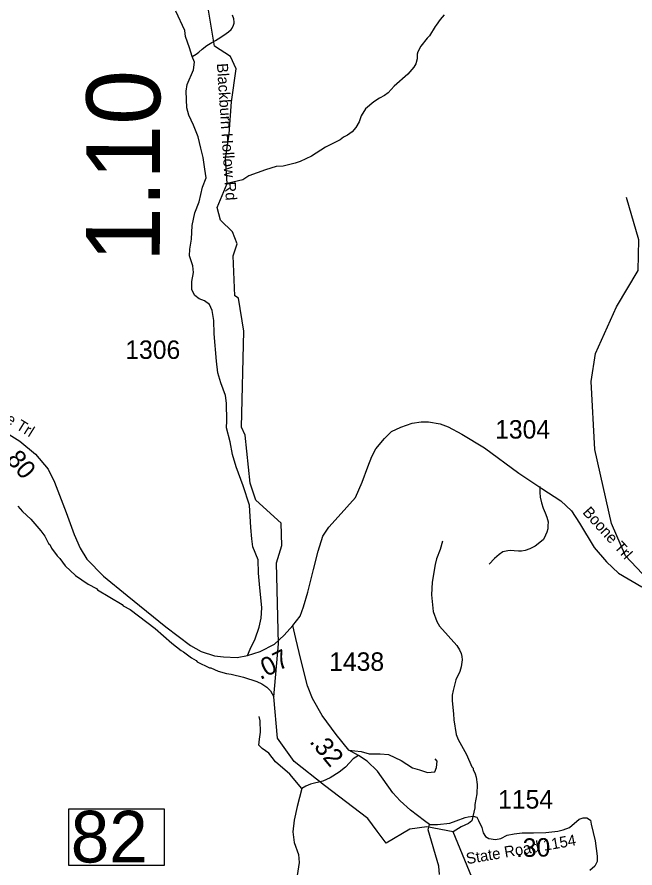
# Model space of a CAD drawing. Extents: x 1248224 to 1454986, y 825081 to 985870.
# Drawn here: x 1310144 to 1314327, y 885943 to 891703 of the extents above; entities that cross this region are included whole.
import ezdxf

# ---------------------------------------------------------------- set-up
doc = ezdxf.new("R2010")
doc.units = 0
for name, color, linetype in [('Exist Hydrographic Creek Single Shore', 7, 'Continuous'), ('Exist Hydrographic Misc Water Feature', 7, 'Continuous'), ('Exist Road Non-System Type 51', 7, 'Continuous'), ('Exist Road Secondary Mileage Hundredths English Label', 7, 'Continuous'), ('Exist Road Secondary Structure Standard Bridge Number Label', 7, 'Continuous'), ('Exist Road Secondary Type 41 Attributed', 7, 'Continuous'), ('Exist Road Secondary Type 51 Attributed', 7, 'Continuous'), ('Exist Road Secondary Type 51 Label', 7, 'Continuous'), ('Exist Road Secondary Type 51 Number Label', 7, 'Continuous')]:
    doc.layers.add(name, color=color, linetype=linetype)

msp = doc.modelspace()

# ---------------------------------------------------------------- linework, layer by layer
at = {"layer": 'Exist Hydrographic Creek Single Shore'}
for points in [[(1311907.8, 886821.5), (1311883.5, 887102.1), (1311913.1, 887460.4), (1311901.1, 888008.9), (1311937.1, 888126.3), (1311932, 888277.4), (1311761, 888431.9), (1311722.1, 888547.6), (1311688, 888873.3), (1311664, 888926.3), (1311679, 889576), (1311643, 889799.9), (1311618, 889816.9), (1311608.1, 890086.3), (1311634, 890167.7), (1311603, 890250.5), (1311522, 890327.6), (1311498.1, 890413.5), (1311567.8, 890576.8), (1311556, 890743.8), (1311579.4, 890912), (1311595.7, 891130), (1311628.4, 891353.6), (1311590.3, 891435.3), (1311482, 891507), (1311438, 891763.9)], [(1313592.1, 885795.1), (1313391.9, 885824.4), (1313221.7, 885881.2), (1313095.9, 886188.8), (1312918, 886222.1), (1312803.6, 886205.8), (1312643.6, 886111.4), (1312581.7, 886193)]]:
    msp.add_lwpolyline(points, dxfattribs=at)
at = {"layer": 'Exist Hydrographic Misc Water Feature'}
for points in [[(1313036.2, 891718), (1313007.3, 891686.8), (1312982.1, 891647.5), (1312973.9, 891639.7), (1312936.1, 891576.9), (1312919.7, 891561.3), (1312878.1, 891506.5), (1312857, 891467.2), (1312852.6, 891451.3), (1312853.7, 891419.3), (1312842.8, 891387.6), (1312830.1, 891364), (1312788.8, 891317.2), (1312696.4, 891235.9), (1312657.1, 891191.1), (1312632.6, 891171.8), (1312598.1, 891154.8), (1312559.4, 891129.9), (1312502, 891081.6), (1312474.6, 891034.4), (1312459.6, 890994.8), (1312438.5, 890955.5), (1312413.6, 890926.1), (1312380.9, 890903.1), (1312354.6, 890889.9), (1312332, 890872.5), (1312232.6, 890821.5), (1312136.9, 890762.2), (1312059.8, 890724.5), (1312027.4, 890713.4), (1311946.8, 890693.7), (1311898.8, 890691.2), (1311826.2, 890669.2), (1311713, 890628.5), (1311672.2, 890601.8), (1311567.8, 890576.8)], [(1315613.2, 885905.6), (1315634.2, 886089), (1315686.2, 886179.8), (1315689.2, 886321), (1315487.1, 886567.9), (1315408.2, 886796.1), (1315303.2, 886913.1), (1315040.1, 887069.4), (1314905.2, 887380.6), (1314710.2, 887594.7), (1314680.2, 887736.5), (1314647.1, 887779.8), (1314376.2, 887936.2), (1314262.2, 888056.7), (1314167.1, 888275.3), (1314054.1, 888776.5), (1314031.1, 889236.7), (1314060.1, 889426.4), (1314201.1, 889742), (1314349.1, 889988.6), (1314354.1, 890195.3), (1314269.1, 890482.6)], [(1310149.5, 888392.4), (1310180.4, 888355.5), (1310237, 888303.9), (1310304.8, 888226), (1310331.7, 888189.2), (1310358.4, 888140.4), (1310366.2, 888132.2), (1310377.5, 888107.9), (1310416.1, 888056.9), (1310433.6, 888038.3), (1310470.3, 887989.3), (1310540.4, 887923.3), (1310626.8, 887864.8), (1310682, 887835.2), (1310689.8, 887827), (1310855, 887726.2), (1310862.7, 887718), (1310910.1, 887692.7), (1311078.5, 887563.8), (1311191.7, 887464.6), (1311254.4, 887414.7), (1311270.2, 887406.3), (1311325, 887364.8), (1311356.6, 887347.9), (1311364.3, 887339.6), (1311447.2, 887297.2), (1311455.1, 887297), (1311506.6, 887275.5), (1311562.2, 887259.9), (1311594, 887255), (1311677.5, 887234.6), (1311766.7, 887206), (1311802.3, 887189), (1311835.7, 887166.1), (1311859, 887141.4), (1311883.5, 887102.1)], [(1313024, 888155.4), (1313008.4, 888099.8), (1312984.6, 888036.6), (1312973.5, 887996.9), (1312954.2, 887877.5), (1312949.7, 887791.6), (1312960.5, 887679.4), (1312984.7, 887612.7), (1313003.8, 887580.2), (1313120.1, 887448.9), (1313139.3, 887420.3), (1313150.7, 887396), (1313156.1, 887375.8), (1313157.5, 887351.8), (1313150.1, 887304), (1313141.2, 887272.3), (1313113.6, 887217.1), (1313095.6, 887145.6), (1313090.7, 887113.8), (1313089.6, 887073.8), (1313099.1, 886985.6), (1313099.9, 886945.6), (1313117.3, 886847.1), (1313130.3, 886812.7), (1313187.4, 886711.1), (1313223.1, 886628.2), (1313230.9, 886617.9), (1313230.6, 886609.9), (1313245.8, 886581.5), (1313253.1, 886557.3), (1313257.7, 886509.1), (1313256, 886445.2), (1313244, 886373.6), (1313243.3, 886349.6), (1313222.9, 886262.2), (1313200.3, 886244.9), (1313149.7, 886222.4), (1313095.9, 886188.8)], [(1312581.7, 886193), (1312517.9, 886277.1), (1312225.1, 886502.1), (1312020.1, 886663.8), (1311907.8, 886821.5)]]:
    msp.add_lwpolyline(points, dxfattribs=at)
at = {"layer": 'Exist Road Non-System Type 51'}
for points in [[(1311330, 891437.1), (1311356.3, 891452.4), (1311374.6, 891466.1), (1311397, 891485.6), (1311429.8, 891510.8), (1311462.2, 891532.1), (1311488.5, 891545.4), (1311504.9, 891555.1), (1311531.3, 891572.6), (1311559.7, 891591.8), (1311575.9, 891603.5), (1311594.4, 891619.1), (1311600.6, 891628.8), (1311609, 891648.7), (1311613.3, 891662.6), (1311613.4, 891668.6), (1311612.1, 891690.6), (1311602.6, 891716.8)], [(1313684, 888524.4), (1313682.9, 888484.3), (1313686.1, 888454.3), (1313693.3, 888414.1), (1313706.5, 888379.8), (1313719.8, 888347.3), (1313731, 888317.1), (1313738.4, 888286.9), (1313737.7, 888258.9), (1313737.3, 888238.9), (1313730.8, 888217), (1313722.2, 888197.2), (1313713.9, 888181.3), (1313705.6, 888165.5), (1313685.2, 888148.1), (1313670.8, 888138.4), (1313650.4, 888120.8), (1313616.1, 888103.7), (1313583.8, 888092.3), (1313559.7, 888087), (1313537.7, 888087.4), (1313509.7, 888090.2), (1313485.8, 888092.7), (1313465.7, 888091.1), (1313433.4, 888083.9), (1313407, 888064.4), (1313376.4, 888039.2), (1313339.4, 887999.9)], [(1312071.4, 886480.7), (1311991.3, 886577.8), (1311894.2, 886662.9), (1311848.1, 886721.1), (1311804.4, 886752.7), (1311780.2, 886774.6), (1311785, 886815.9), (1311792.3, 886862), (1311789.9, 886939.7), (1311782.6, 886968.9)], [(1312390.9, 886741.7), (1312430.6, 886735.7), (1312474.3, 886730.9), (1312527.7, 886716.3), (1312602.9, 886716.3), (1312658.7, 886711.4), (1312743.7, 886670.1), (1312821.3, 886621.6), (1312867.5, 886607), (1312923.3, 886590), (1312971.8, 886594.8), (1312984, 886624), (1312988.8, 886665.3), (1312974.3, 886682.3)], [(1312454.9, 886705.7), (1312418.5, 886682.3), (1312367.5, 886626.4), (1312323.8, 886592.4), (1312263.1, 886553.6), (1312214.6, 886531.7), (1312129.6, 886509.8), (1312098.1, 886497.7), (1312071.4, 886480.7)], [(1312071.4, 886480.7), (1312040.5, 886360.3), (1312021.1, 886268), (1312011.4, 886187.8), (1312021.1, 886115), (1312050.2, 886034.8), (1312055.1, 885981.4), (1312028.4, 885821.1)]]:
    msp.add_lwpolyline(points, dxfattribs=at)
at = {"layer": 'Exist Road Secondary Structure Standard Bridge Number Label'}
msp.add_lwpolyline([(1310495.6, 886343), (1311139.7, 886343), (1311139.7, 885960.7), (1310495.6, 885960.7)], close=True, dxfattribs=at)
at = {"layer": 'Exist Road Secondary Type 41 Attributed'}
msp.add_lwpolyline([(1311703.3, 887381.1), (1311721.9, 887425), (1311756.4, 887494.1), (1311782.8, 887573.3), (1311797, 887634.3), (1311801.1, 887703.4), (1311784.9, 887863.9), (1311778.8, 887939.1), (1311776.7, 888028.5), (1311740.2, 888117.9), (1311734.1, 888170.7), (1311726, 888247.9), (1311717.9, 888399.2), (1311675.2, 888529.2), (1311626.5, 888659.3), (1311602.1, 888742.6), (1311587.9, 888827.9), (1311561.8, 888922.3), (1311563.9, 888969.1), (1311561.8, 889088.9), (1311555.8, 889141.8), (1311523.3, 889227.1), (1311503, 889294.2), (1311494.9, 889373.4), (1311478.6, 889559.2), (1311476.6, 889648.6), (1311464.4, 889717.6), (1311446.2, 889758.3), (1311413.7, 889782.7), (1311377.1, 889796.9), (1311348.7, 889819.2), (1311328.4, 889857.8), (1311326.4, 889912.7), (1311338.5, 889973.7), (1311334.7, 890019.3), (1311312.4, 890086.4), (1311314.4, 890131.1), (1311324.6, 890200.2), (1311330.7, 890291.6), (1311348.9, 890379), (1311377.3, 890452.1), (1311399.7, 890551.7), (1311423.6, 890615.8), (1311415.5, 890672.7), (1311403.3, 890751.9), (1311389.1, 890814.9), (1311370.8, 890892.1), (1311338.4, 890971.4), (1311307.9, 891038.4), (1311293.7, 891089.2), (1311289.7, 891201.8), (1311295.8, 891246.5), (1311338.4, 891346.1), (1311344.5, 891398.9), (1311330, 891437.1), (1311312, 891494.4), (1311285.6, 891571.6), (1311279.5, 891612.2), (1311218.6, 891742.3)], dxfattribs=at)
at = {"layer": 'Exist Road Secondary Type 51 Attributed'}
for points in [[(1310027.1, 888916.7), (1310164.4, 888832.2), (1310269.1, 888744.1), (1310354, 888643.9), (1310398.1, 888554.3), (1310477, 888349.3), (1310531.3, 888201.2), (1310570.7, 888108.6), (1310617.8, 888034.2), (1310730.1, 887918.8), (1310889.4, 887788.1), (1311151.5, 887575), (1311318.4, 887449), (1311389.7, 887409.5), (1311480.8, 887379.1), (1311542.4, 887372), (1311633.5, 887369), (1311703.3, 887381.1)], [(1312011.3, 887583.9), (1312060.7, 887647.6), (1312084.4, 887711.7), (1312113.7, 887810.6), (1312151, 887962.7), (1312181.7, 888086.8), (1312215.1, 888188.5), (1312255.5, 888249.8), (1312318.2, 888319.5), (1312434.9, 888451.2), (1312480.8, 888555.8), (1312519.8, 888658.9), (1312544.9, 888728.6), (1312572.7, 888781.5), (1312631.2, 888851.2), (1312678.6, 888897.2), (1312741.7, 888926.3), (1312819.7, 888954.2), (1312879.6, 888963.9), (1312929.7, 888963.9), (1313009.1, 888948.6), (1313062, 888929.1), (1313153.9, 888878.9), (1313309.3, 888787.7), (1313541.8, 888614.8), (1313696.4, 888513.1), (1313824.5, 888429.5), (1313898.3, 888359.8), (1313952.3, 888276.7), (1314051.2, 888112.3), (1314134.7, 888016.1), (1314216.4, 887939.9), (1314372.3, 887846.5)], [(1311703.3, 887381.1), (1311789.8, 887409.2), (1311886.9, 887457.8), (1311953.6, 887520.1), (1312011.3, 887583.9)], [(1312937.2, 886236.7), (1312902.2, 886263.1), (1312807.7, 886335.2), (1312738.2, 886397.4), (1312688.5, 886452.1), (1312584.1, 886598.8), (1312514.6, 886665.9), (1312454.9, 886705.7), (1312390.9, 886741.7), (1312304, 886846.2), (1312209.6, 886975.5), (1312145, 887089.8), (1312110.2, 887176.9), (1312065.5, 887353.4), (1312030.7, 887497.6), (1312011.3, 887583.9)], [(1312937.2, 886236.7), (1312990.9, 886237.7), (1313072.8, 886246.4), (1313116.3, 886261.3), (1313177.2, 886285), (1313197.1, 886289.9), (1313230.6, 886293.7), (1313255.5, 886286.2), (1313267.9, 886265.1), (1313290.2, 886216.6), (1313298.9, 886181.8), (1313315.1, 886155.7), (1313337.4, 886143.2), (1313382.2, 886137), (1313418.2, 886143.2), (1313462.9, 886164.4), (1313508.9, 886174.3), (1313562.3, 886180.5), (1313639.3, 886181.8), (1313723, 886184.3), (1313803.8, 886193), (1313839.8, 886200.5), (1313884.5, 886217.9), (1313949.1, 886272.6), (1313975.2, 886283.8), (1314000.1, 886283.8), (1314024.9, 886267.6), (1314031.1, 886240.3), (1314057.2, 886127.1), (1314070.9, 886022.7), (1314070.9, 885986.7), (1314056, 885955.6), (1314021.3, 885925.8)], [(1313004.3, 885898.5), (1312999.3, 885955.7), (1312927.3, 886201.8), (1312937.2, 886236.7)]]:
    msp.add_lwpolyline(points, dxfattribs=at)

# ---------------------------------------------------------------- texts
at = {"layer": 'Exist Road Secondary Mileage Hundredths English Label'}
for s, height, rotation, p in [('1.10', 500, 89.84754, (1311110.6, 890043.5)), ('.80', 125, 310.29157, (1310036.5, 888741.8)), ('.07', 125, 26.58324, (1311790.6, 887214.8)), ('.32', 125, 309.78312, (1312119.3, 886796.5)), ('.30', 125, 0.92433, (1313522.1, 886017.3))]:
    msp.add_text(s, height=height, rotation=rotation, dxfattribs=at).set_placement(p)
at = {"layer": 'Exist Road Secondary Structure Standard Bridge Number Label'}
msp.add_text('82', height=350, dxfattribs=at).set_placement((1310508.2, 885980.5))
at = {"layer": 'Exist Road Secondary Type 51 Label'}
for s, rotation, p in [('Blackburn Hollow Rd', 273.78026, (1311496.7, 891388.3)), ('Boone Trl', 328.06264, (1309862.5, 889087.2)), ('Boone Trl', 312.30316, (1313968.3, 888347.4)), ('State Road 1154', 9.82659, (1313190.5, 885968.7))]:
    msp.add_text(s, height=75, rotation=rotation, dxfattribs=at).set_placement(p)
at = {"layer": 'Exist Road Secondary Type 51 Number Label'}
for s, p in [('1306', (1310877.2, 889389.2)), ('1304', (1313380.5, 888849.9)), ('1438', (1312257.1, 887277.7)), ('1154', (1313400.4, 886345.2))]:
    msp.add_text(s, height=125, dxfattribs=at).set_placement(p)

doc.saveas('drawing.dxf')
